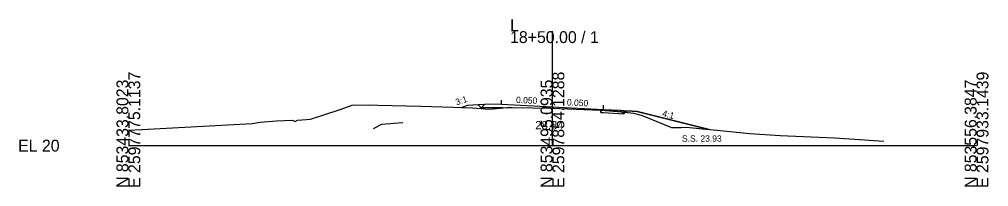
# Model space of a CAD drawing. Extents: x -26 to 1203, y -10 to 9526.
# Drawn here: x -25.7 to 202.8, y 8490.3 to 8529.9 of the extents above; entities that cross this region are included whole.
import ezdxf

# ---------------------------------------------------------------- set-up
doc = ezdxf.new("R2010")
doc.units = 0
for name, color, linetype in [('Default', 7, 'Continuous'), ('Exist Cross Section Cell', 7, 'Continuous'), ('Exist XS Center Line Elevation Label', 7, 'Continuous'), ('Exist XS Ground Line', 7, 'Continuous'), ('Prop XS Earthwork Shape', 7, 'Continuous'), ('Prop XS EOT Tick Mark', 7, 'Continuous'), ('Prop XS Finish Grade', 7, 'Continuous'), ('Prop XS Finish Grade Earthwork', 7, 'Continuous'), ('Prop XS Finish Grade Paved Shoulder', 7, 'Continuous'), ('Prop XS Finish Grade Pavement', 7, 'Continuous'), ('Prop XS Pvmt Edge Slope', 7, 'Continuous'), ('Prop XS SE Text', 7, 'Continuous'), ('Prop XS Side Slope Text', 7, 'Continuous'), ('Prop XS SS Elevation Text', 7, 'Continuous'), ('Prop XS Subgrade Earthwork', 7, 'Continuous')]:
    doc.layers.add(name, color=color, linetype=linetype)

msp = doc.modelspace()

# ---------------------------------------------------------------- linework, layer by layer
at = {"layer": 'Default'}
for p, q in [((59.69, 8504.96), (57.69, 8503.96)), ((64.69, 8505.37), (59.69, 8504.96))]:
    msp.add_line(p, q, dxfattribs=at)
at = {"layer": 'Exist Cross Section Cell'}
for p, q in [((100, 8500), (100, 8527.05)), ((0, 8500), (100, 8500)), ((100, 8500), (200, 8500))]:
    msp.add_line(p, q, dxfattribs=at)
at = {"layer": 'Exist XS Ground Line'}
for p, q in [((42.92, 8506.24), (49.93, 8508.57)), ((49.93, 8508.57), (52.79, 8509.53)), ((52.79, 8509.53), (56.79, 8509.65)), ((56.79, 8509.65), (58.79, 8509.6)), ((58.79, 8509.6), (68.96, 8509.31)), ((68.96, 8509.31), (79.14, 8509.02)), ((79.14, 8509.02), (81.14, 8508.97)), ((81.14, 8508.97), (85.14, 8508.65)), ((85.14, 8508.65), (89.29, 8509.02)), ((89.29, 8509.02), (90.53, 8509.01)), ((90.53, 8509.01), (100, 8508.84)), ((100, 8508.84), (100.32, 8508.83)), ((100.32, 8508.83), (101.65, 8508.77)), ((101.65, 8508.77), (111.42, 8508.35)), ((111.42, 8508.35), (115.38, 8508.05)), ((34.94, 8505.84), (38.69, 8506.03)), ((38.69, 8506.03), (39.35, 8505.7)), ((39.35, 8505.7), (39.92, 8505.99)), ((39.92, 8505.99), (42.92, 8506.24)), ((115.38, 8508.05), (119.07, 8507.7)), ((119.07, 8507.7), (120.9, 8507.2)), ((120.9, 8507.2), (121.91, 8506.82)), ((121.91, 8506.82), (124.64, 8505.69)), ((0, 8503.63), (3.2, 8503.82)), ((3.2, 8503.82), (29.17, 8505.22)), ((29.17, 8505.22), (31.06, 8505.54)), ((31.06, 8505.54), (34.94, 8505.84)), ((124.64, 8505.69), (128.04, 8504.29)), ((128.04, 8504.29), (130.35, 8504.32)), ((130.35, 8504.32), (131.52, 8504.36)), ((131.52, 8504.36), (138.77, 8503.64)), ((138.77, 8503.64), (146.55, 8502.88)), ((146.55, 8502.88), (153.67, 8502.42)), ((153.67, 8502.42), (166.52, 8501.86)), ((166.52, 8501.86), (172.38, 8501.43)), ((172.38, 8501.43), (178.17, 8501.08))]:
    msp.add_line(p, q, dxfattribs=at)
at = {"layer": 'Prop XS Earthwork Shape'}
for points in [[(80, 8509.5), (78.62, 8509.04), (79.14, 8509.02), (81.14, 8508.97), (85.14, 8508.65), (88.29, 8508.93), (88, 8508.94), (83.21, 8508.94), (82.51, 8509.65)], [(89.28, 8508.87), (88.29, 8508.93), (89.28, 8509.02)], [(116.84, 8507.53), (117.19, 8507.88), (115.38, 8508.05), (111.42, 8508.35), (111.4, 8508.35), (111.4, 8507.86), (112, 8507.82)], [(128.04, 8504.29), (130.35, 8504.32), (131.52, 8504.36), (136.93, 8503.82), (120, 8508.06), (117.56, 8508.25), (117.19, 8507.88), (119.07, 8507.7), (120.9, 8507.2), (121.91, 8506.82), (124.64, 8505.69)]]:
    msp.add_lwpolyline(points, close=True, dxfattribs=at)
at = {"layer": 'Prop XS EOT Tick Mark'}
for p, q in [((88, 8509.78), (88, 8510.78)), ((112, 8508.58), (112, 8509.58))]:
    msp.add_line(p, q, dxfattribs=at)
at = {"layer": 'Prop XS Finish Grade'}
for p, q in [((84, 8509.74), (82.51, 8509.65)), ((116, 8508.38), (117.56, 8508.25))]:
    msp.add_line(p, q, dxfattribs=at)
at = {"layer": 'Prop XS Finish Grade Earthwork'}
for p, q in [((80, 8509.5), (78.62, 8509.04)), ((82.51, 8509.65), (80, 8509.5)), ((117.56, 8508.25), (120, 8508.06)), ((120, 8508.06), (136.93, 8503.82))]:
    msp.add_line(p, q, dxfattribs=at)
at = {"layer": 'Prop XS Finish Grade Paved Shoulder'}
for p, q in [((88, 8509.78), (84, 8509.74)), ((112, 8508.58), (116, 8508.38))]:
    msp.add_line(p, q, dxfattribs=at)
at = {"layer": 'Prop XS Finish Grade Pavement'}
for p, q in [((88, 8509.78), (100, 8509.18)), ((100, 8509.18), (112, 8508.58))]:
    msp.add_line(p, q, dxfattribs=at)
at = {"layer": 'Prop XS Pvmt Edge Slope'}
for p, q in [((84, 8509.74), (83.21, 8508.94)), ((116, 8508.38), (116.84, 8507.53))]:
    msp.add_line(p, q, dxfattribs=at)
at = {"layer": 'Prop XS Subgrade Earthwork'}
for p, q in [((83.21, 8508.94), (82.51, 8509.65)), ((88, 8508.94), (83.21, 8508.94)), ((89.28, 8508.87), (88, 8508.94)), ((89.28, 8509.02), (89.28, 8508.87)), ((111.4, 8507.86), (111.4, 8508.35)), ((111.4, 8507.86), (112, 8507.82)), ((112, 8507.82), (116.84, 8507.53)), ((116.84, 8507.53), (117.56, 8508.25))]:
    msp.add_line(p, q, dxfattribs=at)

# ---------------------------------------------------------------- texts
at = {"layer": 'Exist Cross Section Cell'}
for s, p in [('L', (90, 8527.05)), ('18+50.00 / 1', (90, 8524.25)), ('EL 20', (-26, 8498.6))]:
    msp.add_text(s, height=2.8, dxfattribs=at).set_placement(p)
for s, p in [('N 853433.8023', (0, 8490)), ('E 2597775.1137', (2.8, 8490)), ('N 853495.0935', (100, 8490)), ('E 2597854.1288', (102.8, 8490)), ('N 853556.3847', (200, 8490)), ('E 2597933.1439', (202.8, 8490))]:
    msp.add_text(s, height=2.8, rotation=90, dxfattribs=at).set_placement(p)
at = {"layer": 'Exist XS Center Line Elevation Label'}
msp.add_text('28.84', height=2, dxfattribs=at).set_placement((95.93, 8503.84))
at = {"layer": 'Prop XS SE Text'}
for p in [(91.38, 8510.11), (103.38, 8509.51)]:
    msp.add_text('0.050', height=1.5, rotation=357.1376, dxfattribs=at).set_placement(p)
at = {"layer": 'Prop XS Side Slope Text'}
for s, rotation, p in [('3:1', 18.4349, (77.42, 8509.51)), ('4:1', 345.9638, (125.79, 8506.94))]:
    msp.add_text(s, height=1.5, rotation=rotation, dxfattribs=at).set_placement(p)
at = {"layer": 'Prop XS SS Elevation Text'}
msp.add_text('S.S. 23.93', height=1.5, dxfattribs=at).set_placement((130.54, 8500.93))

doc.saveas('drawing.dxf')
